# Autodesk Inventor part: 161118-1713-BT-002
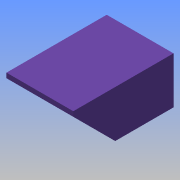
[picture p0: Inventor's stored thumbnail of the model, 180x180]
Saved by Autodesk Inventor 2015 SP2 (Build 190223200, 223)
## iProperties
Created: 2016-11
Part Number: 161118-1713-BT-002
Material: Generisch
Document SubType Name: Modeling
Designer: MP
Mass: 352.196 g
Surface Area: 731.084 cm^2
Volume: 352.196 cm^3
Density: 1 g/cm^3
Appearance: Violett
Author: MP
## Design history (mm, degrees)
sketch "Skizze1"
  geometry: L1 (-50, 150)-(50, 150); L2 (50, 150)-(50, 0); L3 (50, 0)-(-50, 0); L4 (-50, 0)-(-50, 150); C1 r 30 at (0, 90); 2 further points
  constraints: 8 end point, 2 parallel, 1 centre point, 1 coincident, 1 horizontal, 1 midpoint, 1 perpendicular, 1 vertical alignment
  dimensions: "d0" = 100 distance of L2.end L3.end; "d1" = 150 distance of L3.end L1.start; "d2" = 60 diameter of C1; "d3" = 90 distance of point (0, 0) C1.centre
extrude "Extrusion1" new body sketch "Skizze1" distance "d5" = 20; taper "d6" = 0 deg
extrude "Extrusion2" join sketch "Skizze1" distance "d7" = 10; taper "d8" = 0 deg
feature "Extrusionsfläche1" dims "d11" = 50, "d12" = 0
feature "Verdickung1" dims "d13" = 2, "d14" = 2
chamfer "Fase1" distance "d15" = 62.75; stored, may be unused: second distance "d16" = 2, angle "d17" = 45 deg
node "Volumenkörper1"
node "Fläche1"
